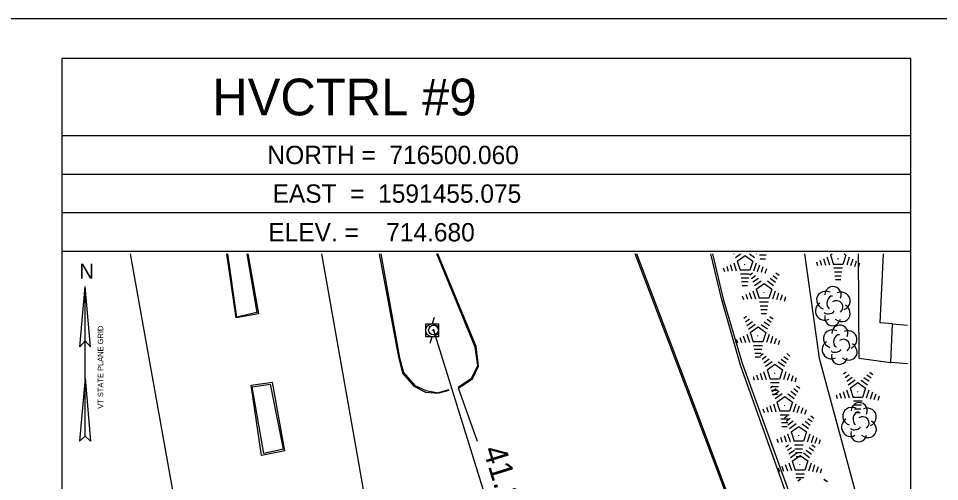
# Model space of a CAD drawing. Extents: x 1586965 to 1590952, y 716317 to 720029.
# Drawn here: x 1590701.5 to 1590820.9, y 716551.1 to 716611 of the extents above; entities that cross this region are included whole.
import ezdxf

# ---------------------------------------------------------------- set-up
doc = ezdxf.new("R2010")
doc.units = 0
for name, color, linetype in [('CBP', 7, 'Continuous'), ('Default', 7, 'Continuous'), ('LBF', 7, 'Continuous'), ('LS', 7, 'Continuous'), ('LSH', 7, 'Continuous'), ('LTC', 7, 'Continuous'), ('LW', 7, 'Continuous'), ('LWS', 7, 'Continuous'), ('NBL2', 7, 'Continuous'), ('NNA_P', 7, 'Continuous'), ('PET', 7, 'Continuous'), ('RC', 7, 'Continuous'), ('RDP', 7, 'Continuous'), ('RSW', 7, 'Continuous'), ('UP', 7, 'Continuous')]:
    doc.layers.add(name, color=color, linetype=linetype)

msp = doc.modelspace()

# ---------------------------------------------------------------- linework, layer by layer
at = {"layer": 'CBP'}
for radius in [0.625, 0.0833]:
    msp.add_circle((1590755.32, 716570.71), radius, dxfattribs=at)
at = {"layer": 'Default'}
msp.add_line((1590755.32, 716570.71), (1590767.54, 716531.39), dxfattribs=at)
at = {"layer": 'LBF'}
msp.add_lwpolyline([(1590816.72, 716566.34), (1590814.58, 716566.5), (1590814.8, 716571.53), (1590816.72, 716571.34)], dxfattribs=at)
at = {"layer": 'LS'}
for points in [[(1590731.12, 716580.57), (1590732.43, 716572.99), (1590729.83, 716572.39), (1590728.68, 716580.57)], [(1590735.9, 716555.28), (1590733.33, 716554.73), (1590731.81, 716563.38), (1590734.22, 716563.7)], [(1590735.9, 716555.28), (1590734.22, 716563.7)]]:
    msp.add_lwpolyline(points, dxfattribs=at)
at = {"layer": 'LSH'}
for p, q in [((1590807.04, 716573.86), (1590807.04, 716573.86)), ((1590807.04, 716573.86), (1590807.04, 716573.86)), ((1590807.93, 716568.86), (1590807.93, 716568.86)), ((1590807.93, 716568.86), (1590807.93, 716568.86)), ((1590810.43, 716558.84), (1590810.43, 716558.84)), ((1590810.43, 716558.84), (1590810.43, 716558.84))]:
    msp.add_line(p, q, dxfattribs=at)
for centre in [(1590807.09, 716575.29), (1590807.97, 716570.3), (1590810.48, 716560.28)]:
    msp.add_arc(centre, 1.05, 335.5272, 180.9563, dxfattribs=at)
for centre, major_axis, ratio, start_param, end_param in [((1590806.25, 716574.52), (1.21, -0.51), 0.895232, 1.570796, 4.712389), ((1590806.83, 716574.31), (-0.208, -0.792), 0.645439, 3.141593, 6.283185), ((1590808.08, 716574.44), (-1.14, -0.48), 0.949671, 1.570796, 4.712389), ((1590805.96, 716573.15), (0.58, -1.04), 0.959034, 3.141593, 6.283185), ((1590807.54, 716573.69), (-0.5, 0.667), 0.989748, 3.141593, 6.283185), ((1590808.04, 716573.02), (-1.09, 0.79), 0.841452, 1.570796, 4.712389), ((1590806.58, 716573.1), (-0.625, -0.083), 0.423636, 0, 3.141593), ((1590807.04, 716572.36), (0.26, 1.06), 0.942809, 1.570796, 4.712389), ((1590807.13, 716569.53), (1.21, -0.51), 0.895232, 1.570796, 4.712389), ((1590808.97, 716569.44), (-1.14, -0.48), 0.949671, 1.570796, 4.712389), ((1590806.84, 716568.15), (0.58, -1.04), 0.959034, 3.141593, 6.283185), ((1590807.72, 716569.32), (-0.208, -0.792), 0.645439, 3.141593, 6.283185), ((1590808.43, 716568.69), (-0.5, 0.667), 0.989748, 3.141593, 6.283185), ((1590807.47, 716568.11), (-0.625, -0.083), 0.423636, 0, 3.141593), ((1590808.93, 716568.03), (-1.09, 0.79), 0.841452, 1.570796, 4.712389), ((1590807.93, 716567.36), (0.26, 1.06), 0.942809, 1.570796, 4.712389), ((1590809.64, 716559.51), (1.21, -0.51), 0.895232, 1.570796, 4.712389), ((1590811.48, 716559.43), (-1.14, -0.48), 0.949671, 1.570796, 4.712389), ((1590810.23, 716559.3), (-0.208, -0.792), 0.645439, 3.141593, 6.283185), ((1590810.93, 716558.68), (-0.5, 0.667), 0.989748, 3.141593, 6.283185), ((1590809.35, 716558.13), (0.58, -1.04), 0.959034, 3.141593, 6.283185), ((1590811.43, 716558.01), (-1.09, 0.79), 0.841452, 1.570796, 4.712389), ((1590810.43, 716557.34), (0.26, 1.06), 0.942809, 1.570796, 4.712389), ((1590809.98, 716558.09), (-0.625, -0.083), 0.423636, 0, 3.141593)]:
    msp.add_ellipse(centre, major_axis=major_axis, ratio=ratio, start_param=start_param, end_param=end_param, dxfattribs=at)
at = {"layer": 'LTC'}
for p, q in [((1590794.24, 716580.55), (1590794.26, 716580.57)), ((1590794.45, 716580.09), (1590795.12, 716580.57)), ((1590794.67, 716579.63), (1590795.69, 716580.37)), ((1590795.69, 716580.37), (1590796.68, 716579.64)), ((1590796.26, 716580.57), (1590796.92, 716580.09)), ((1590797.11, 716580.57), (1590797.16, 716580.53)), ((1590798.41, 716580.39), (1590797.58, 716580.39)), ((1590798.33, 716579.89), (1590797.65, 716579.89)), ((1590805.84, 716579.96), (1590806.11, 716579.12)), ((1590806.3, 716580.18), (1590806.63, 716579.16)), ((1590806.75, 716580.4), (1590806.99, 716580.57)), ((1590806.75, 716580.4), (1590807.14, 716579.2)), ((1590808.76, 716580.41), (1590808.37, 716579.2)), ((1590808.53, 716580.57), (1590808.76, 716580.41)), ((1590809.2, 716580.13), (1590808.86, 716579.09)), ((1590809.64, 716579.88), (1590809.35, 716579)), ((1590792.85, 716578.76), (1590793.01, 716578.3)), ((1590793.31, 716578.98), (1590793.52, 716578.33)), ((1590793.76, 716579.2), (1590794.04, 716578.36)), ((1590794.22, 716579.41), (1590794.55, 716578.39)), ((1590794.67, 716579.63), (1590795.06, 716578.44)), ((1590796.68, 716579.64), (1590796.29, 716578.44)), ((1590797.12, 716579.37), (1590796.78, 716578.33)), ((1590797.57, 716579.12), (1590797.28, 716578.24)), ((1590798.01, 716578.87), (1590797.77, 716578.14)), ((1590798.45, 716578.62), (1590798.27, 716578.05)), ((1590804.93, 716579.53), (1590805.08, 716579.06)), ((1590805.39, 716579.74), (1590805.6, 716579.09)), ((1590808.37, 716579.2), (1590807.14, 716579.2)), ((1590808.33, 716578.7), (1590807.19, 716578.7)), ((1590810.09, 716579.63), (1590809.85, 716578.9)), ((1590810.53, 716579.38), (1590810.34, 716578.81)), ((1590796.29, 716578.44), (1590795.06, 716578.44)), ((1590796.25, 716577.94), (1590795.11, 716577.94)), ((1590796.17, 716577.44), (1590795.18, 716577.44)), ((1590796.3, 716577.86), (1590796.65, 716578.12)), ((1590796.51, 716577.4), (1590797.03, 716577.78)), ((1590796.72, 716576.93), (1590797.42, 716577.44)), ((1590799.32, 716577.75), (1590799.87, 716577.36)), ((1590799.69, 716578.1), (1590800.11, 716577.8)), ((1590808.25, 716578.2), (1590807.26, 716578.2)), ((1590808.16, 716577.7), (1590807.33, 716577.7)), ((1590796.09, 716576.94), (1590795.25, 716576.94)), ((1590796, 716576.44), (1590795.33, 716576.44)), ((1590796.92, 716576.47), (1590797.8, 716577.1)), ((1590797.15, 716576.01), (1590798.16, 716576.75)), ((1590798.16, 716576.75), (1590799.16, 716576.02)), ((1590798.58, 716577.06), (1590799.39, 716576.47)), ((1590798.95, 716577.41), (1590799.63, 716576.91)), ((1590808.08, 716577.2), (1590807.4, 716577.2)), ((1590795.33, 716575.14), (1590795.48, 716574.67)), ((1590795.78, 716575.36), (1590796, 716574.71)), ((1590796.24, 716575.58), (1590796.51, 716574.74)), ((1590796.69, 716575.79), (1590797.03, 716574.77)), ((1590797.15, 716576.01), (1590797.54, 716574.82)), ((1590799.16, 716576.02), (1590798.77, 716574.82)), ((1590799.6, 716575.75), (1590799.26, 716574.71)), ((1590800.04, 716575.5), (1590799.75, 716574.61)), ((1590800.48, 716575.25), (1590800.25, 716574.52)), ((1590798.77, 716574.82), (1590797.54, 716574.82)), ((1590798.73, 716574.32), (1590797.58, 716574.32)), ((1590800.93, 716575), (1590800.74, 716574.42)), ((1590798.64, 716573.82), (1590797.66, 716573.82)), ((1590798.56, 716573.32), (1590797.73, 716573.32)), ((1590798.48, 716572.82), (1590797.8, 716572.82)), ((1590795.52, 716572.24), (1590795.87, 716572.5)), ((1590795.73, 716571.77), (1590796.26, 716572.16)), ((1590795.94, 716571.31), (1590796.64, 716571.82)), ((1590796.15, 716570.84), (1590797.02, 716571.48)), ((1590798.17, 716571.78), (1590798.85, 716571.29)), ((1590798.54, 716572.13), (1590799.09, 716571.73)), ((1590798.92, 716572.48), (1590799.33, 716572.18)), ((1590796.37, 716570.39), (1590797.38, 716571.12)), ((1590796.37, 716570.39), (1590796.76, 716569.19)), ((1590797.38, 716571.12), (1590798.38, 716570.4)), ((1590797.8, 716571.44), (1590798.61, 716570.85)), ((1590798.38, 716570.4), (1590797.99, 716569.19)), ((1590794.55, 716569.52), (1590794.7, 716569.05)), ((1590795, 716569.74), (1590795.22, 716569.08)), ((1590795.46, 716569.95), (1590795.73, 716569.12)), ((1590795.92, 716570.17), (1590796.25, 716569.15)), ((1590797.99, 716569.19), (1590796.76, 716569.19)), ((1590798.82, 716570.13), (1590798.48, 716569.09)), ((1590799.26, 716569.88), (1590798.97, 716568.99)), ((1590799.71, 716569.63), (1590799.47, 716568.9)), ((1590800.15, 716569.38), (1590799.96, 716568.8)), ((1590797.95, 716568.69), (1590796.8, 716568.69)), ((1590797.87, 716568.19), (1590796.88, 716568.19)), ((1590797.78, 716567.69), (1590796.95, 716567.69)), ((1590797.7, 716567.19), (1590797.02, 716567.19)), ((1590797.7, 716567.42), (1590798.05, 716567.67)), ((1590797.9, 716566.95), (1590798.43, 716567.33)), ((1590798.11, 716566.48), (1590798.82, 716567)), ((1590800.35, 716566.96), (1590801.03, 716566.47)), ((1590800.72, 716567.31), (1590801.27, 716566.91)), ((1590801.09, 716567.66), (1590801.51, 716567.35)), ((1590798.32, 716566.02), (1590799.2, 716566.66)), ((1590798.55, 716565.56), (1590799.56, 716566.3)), ((1590798.55, 716565.56), (1590798.94, 716564.37)), ((1590799.56, 716566.3), (1590800.56, 716565.57)), ((1590799.98, 716566.61), (1590800.79, 716566.02)), ((1590800.56, 716565.57), (1590800.17, 716564.37)), ((1590796.73, 716564.7), (1590796.88, 716564.23)), ((1590797.18, 716564.91), (1590797.39, 716564.26)), ((1590797.64, 716565.13), (1590797.91, 716564.29)), ((1590798.09, 716565.34), (1590798.42, 716564.33)), ((1590800.17, 716564.37), (1590798.94, 716564.37)), ((1590800.99, 716565.3), (1590800.66, 716564.26)), ((1590801.44, 716565.05), (1590801.15, 716564.17)), ((1590801.88, 716564.8), (1590801.65, 716564.07)), ((1590802.33, 716564.55), (1590802.14, 716563.98)), ((1590808.44, 716565.03), (1590808.8, 716565.29)), ((1590808.65, 716564.57), (1590809.18, 716564.95)), ((1590808.86, 716564.1), (1590809.57, 716564.61)), ((1590811.1, 716564.58), (1590811.78, 716564.08)), ((1590811.47, 716564.92), (1590812.02, 716564.53)), ((1590811.84, 716565.27), (1590812.26, 716564.97)), ((1590798.97, 716563.24), (1590799.32, 716563.5)), ((1590800.13, 716563.87), (1590798.98, 716563.87)), ((1590800.04, 716563.37), (1590799.06, 716563.37)), ((1590799.18, 716562.78), (1590799.71, 716563.16)), ((1590802, 716563.13), (1590802.54, 716562.73)), ((1590802.37, 716563.48), (1590802.79, 716563.18)), ((1590809.07, 716563.64), (1590809.95, 716564.27)), ((1590809.3, 716563.18), (1590810.31, 716563.91)), ((1590809.3, 716563.18), (1590809.68, 716561.99)), ((1590810.31, 716563.91), (1590811.3, 716563.19)), ((1590810.73, 716564.23), (1590811.54, 716563.64)), ((1590811.3, 716563.19), (1590810.91, 716561.99)), ((1590799.96, 716562.87), (1590799.13, 716562.87)), ((1590799.88, 716562.37), (1590799.2, 716562.37)), ((1590799.39, 716562.31), (1590800.09, 716562.82)), ((1590799.6, 716561.84), (1590800.48, 716562.48)), ((1590799.82, 716561.39), (1590800.83, 716562.12)), ((1590800.83, 716562.12), (1590801.83, 716561.4)), ((1590801.25, 716562.44), (1590802.06, 716561.85)), ((1590801.62, 716562.79), (1590802.3, 716562.29)), ((1590807.48, 716562.31), (1590807.63, 716561.84)), ((1590807.93, 716562.53), (1590808.14, 716561.88)), ((1590808.39, 716562.74), (1590808.66, 716561.91)), ((1590808.84, 716562.96), (1590809.17, 716561.94)), ((1590810.91, 716561.99), (1590809.68, 716561.99)), ((1590811.74, 716562.92), (1590811.4, 716561.88)), ((1590812.19, 716562.67), (1590811.9, 716561.78)), ((1590812.63, 716562.42), (1590812.39, 716561.69)), ((1590813.08, 716562.17), (1590812.89, 716561.59)), ((1590798.46, 716560.74), (1590798.67, 716560.09)), ((1590798.91, 716560.95), (1590799.18, 716560.12)), ((1590799.37, 716561.17), (1590799.7, 716560.15)), ((1590799.82, 716561.39), (1590800.21, 716560.2)), ((1590801.83, 716561.4), (1590801.44, 716560.2)), ((1590802.27, 716561.13), (1590801.93, 716560.09)), ((1590802.71, 716560.88), (1590802.42, 716559.99)), ((1590810.88, 716561.49), (1590809.73, 716561.49)), ((1590810.79, 716560.99), (1590809.8, 716560.99)), ((1590798, 716560.52), (1590798.15, 716560.05)), ((1590801.44, 716560.2), (1590800.21, 716560.2)), ((1590801.4, 716559.7), (1590800.26, 716559.7)), ((1590800.8, 716559.37), (1590801.16, 716559.63)), ((1590803.16, 716560.63), (1590802.92, 716559.9)), ((1590803.6, 716560.38), (1590803.41, 716559.8)), ((1590804.2, 716559.61), (1590804.62, 716559.31)), ((1590810.71, 716560.49), (1590809.88, 716560.49)), ((1590810.62, 716559.99), (1590809.95, 716559.99)), ((1590801.32, 716559.2), (1590800.33, 716559.2)), ((1590801.23, 716558.7), (1590800.4, 716558.7)), ((1590801.01, 716558.9), (1590801.54, 716559.29)), ((1590801.22, 716558.44), (1590801.92, 716558.95)), ((1590801.43, 716557.97), (1590802.31, 716558.61)), ((1590803.09, 716558.57), (1590803.9, 716557.98)), ((1590803.46, 716558.91), (1590804.14, 716558.42)), ((1590803.83, 716559.26), (1590804.38, 716558.86)), ((1590801.15, 716558.2), (1590800.47, 716558.2)), ((1590801.2, 716557.3), (1590801.53, 716556.28)), ((1590801.65, 716557.52), (1590802.67, 716558.25)), ((1590801.65, 716557.52), (1590802.04, 716556.32)), ((1590802.67, 716558.25), (1590803.66, 716557.53)), ((1590803.66, 716557.53), (1590803.27, 716556.32)), ((1590804.1, 716557.26), (1590803.76, 716556.22)), ((1590799.83, 716556.65), (1590799.99, 716556.18)), ((1590800.29, 716556.87), (1590800.5, 716556.21)), ((1590800.74, 716557.08), (1590801.02, 716556.25)), ((1590803.27, 716556.32), (1590802.04, 716556.32)), ((1590804.54, 716557.01), (1590804.26, 716556.12)), ((1590804.99, 716556.76), (1590804.75, 716556.03)), ((1590805.43, 716556.51), (1590805.25, 716555.93)), ((1590800.96, 716555.61), (1590801.32, 716555.87)), ((1590801.17, 716555.15), (1590801.7, 716555.53)), ((1590801.38, 716554.68), (1590802.08, 716555.19)), ((1590801.59, 716554.22), (1590802.47, 716554.86)), ((1590803.23, 716555.82), (1590802.09, 716555.82)), ((1590803.15, 716555.32), (1590802.16, 716555.32)), ((1590803.07, 716554.82), (1590802.23, 716554.82)), ((1590803.25, 716554.81), (1590804.06, 716554.22)), ((1590803.62, 716555.16), (1590804.3, 716554.66)), ((1590803.99, 716555.51), (1590804.54, 716555.11)), ((1590804.36, 716555.86), (1590804.78, 716555.55)), ((1590801.36, 716553.54), (1590801.69, 716552.52)), ((1590801.81, 716553.76), (1590802.83, 716554.5)), ((1590801.81, 716553.76), (1590802.2, 716552.57)), ((1590802.98, 716554.32), (1590802.31, 716554.32)), ((1590802.83, 716554.5), (1590803.82, 716553.77)), ((1590803.82, 716553.77), (1590803.43, 716552.57)), ((1590799.99, 716552.89), (1590800.15, 716552.43)), ((1590800.45, 716553.11), (1590800.66, 716552.46)), ((1590800.9, 716553.33), (1590801.18, 716552.49)), ((1590803.43, 716552.57), (1590802.2, 716552.57)), ((1590804.26, 716553.5), (1590803.92, 716552.46)), ((1590804.7, 716553.25), (1590804.42, 716552.37)), ((1590805.15, 716553), (1590804.91, 716552.27)), ((1590805.59, 716552.75), (1590805.41, 716552.18)), ((1590803.39, 716552.07), (1590802.25, 716552.07)), ((1590803.31, 716551.57), (1590802.32, 716551.57)), ((1590802.51, 716551.19), (1590802.87, 716551.44)), ((1590802.54, 716551.18), (1590802.89, 716551.43)), ((1590805.91, 716551.43), (1590806.33, 716551.12)), ((1590805.94, 716551.42), (1590806.36, 716551.11))]:
    msp.add_line(p, q, dxfattribs=at)
at = {"layer": 'LW'}
msp.add_lwpolyline([(1590816.72, 716513.27), (1590815.7, 716513.71), (1590814.67, 716514.44), (1590811.44, 716522.23), (1590806.32, 716536.3), (1590802.62, 716546.4), (1590795.37, 716566.37), (1590792.94, 716574.53), (1590791.51, 716580.57)], dxfattribs=at)
at = {"layer": 'LWS'}
msp.add_lwpolyline([(1590803.38, 716580.57), (1590805.28, 716567.09), (1590811.16, 716545.37), (1590814.07, 716536.23), (1590815.3, 716534.63), (1590816.72, 716534.63)], dxfattribs=at)
at = {"layer": 'NBL2'}
for p, q in [((1590312.19, 716611.03), (1590952.19, 716611.03)), ((1590817.19, 716595.86), (1590707.19, 716595.86)), ((1590817.19, 716590.86), (1590707.19, 716590.86)), ((1590817.19, 716585.86), (1590707.19, 716585.86)), ((1590817.19, 716580.86), (1590707.19, 716580.86))]:
    msp.add_line(p, q, dxfattribs=at)
msp.add_lwpolyline([(1590707.19, 716489.86), (1590817.19, 716489.86), (1590817.19, 716605.86), (1590707.19, 716605.86)], close=True, dxfattribs=at)
at = {"layer": 'NNA_P'}
for p, q in [((1590709.48, 716568.55), (1590710.18, 716576.34)), ((1590710.18, 716556.97), (1590710.18, 716576.34)), ((1590710.87, 716568.55), (1590710.18, 716576.34)), ((1590709.48, 716568.55), (1590710.18, 716569.31)), ((1590710.87, 716568.55), (1590710.18, 716569.31)), ((1590710.18, 716564.49), (1590709.46, 716556.33)), ((1590710.18, 716564.49), (1590710.9, 716556.33)), ((1590710.18, 716556.97), (1590709.46, 716556.33)), ((1590710.18, 716556.97), (1590710.9, 716556.33))]:
    msp.add_line(p, q, dxfattribs=at)
at = {"layer": 'PET'}
for points in [[(1590761.02, 716556.28), (1590758.58, 716563.19), (1590760.37, 716564.4), (1590761.15, 716566.03), (1590760.84, 716568.57), (1590755.88, 716580.57)], [(1590816.72, 716501.87), (1590815.38, 716502.54), (1590813.44, 716503.83), (1590810.82, 716506.6), (1590809.07, 716509.13), (1590807.86, 716511.61), (1590807.26, 716513.17), (1590805.73, 716517.09), (1590799.48, 716533.06), (1590789.21, 716560.16), (1590781.44, 716580.57)]]:
    msp.add_lwpolyline(points, dxfattribs=at)
at = {"layer": 'RC'}
for points in [[(1590748.48, 716580.57), (1590750.92, 716567.1), (1590751.45, 716565.22), (1590752.91, 716563.54), (1590754.31, 716562.87), (1590755.96, 716562.6)], [(1590758.58, 716563.35), (1590760.23, 716564.47), (1590761.07, 716566.13), (1590760.73, 716568.48), (1590755.74, 716580.57)], [(1590816.72, 716502.02), (1590815.53, 716502.54), (1590813.56, 716504.04), (1590811.02, 716506.63), (1590809.18, 716509.24), (1590808, 716511.55), (1590807.33, 716513.31), (1590805.92, 716517.2), (1590799.59, 716533.11), (1590789.46, 716560.15), (1590781.65, 716580.57)], [(1590758.58, 716563.35), (1590758.54, 716563.34)], [(1590757.27, 716562.98), (1590755.96, 716562.6)]]:
    msp.add_lwpolyline(points, dxfattribs=at)
at = {"layer": 'RDP'}
for points in [[(1590716.01, 716580.57), (1590722.65, 716543.71), (1590718.57, 716542.63), (1590720.31, 716531.18), (1590748.7, 716535.86)], [(1590731.25, 716580.57), (1590732.65, 716572.83), (1590729.77, 716572.28), (1590728.56, 716580.57)], [(1590740.82, 716580.57), (1590745.38, 716554.72), (1590748.7, 716535.86)], [(1590748.3, 716580.57), (1590750.77, 716567.22), (1590751.32, 716565.14), (1590752.79, 716563.47), (1590754.27, 716562.69), (1590756.02, 716562.55)], [(1590736.08, 716555.07), (1590733.06, 716554.48), (1590731.69, 716563.58), (1590734.46, 716563.96)], [(1590736.08, 716555.07), (1590734.46, 716563.96)], [(1590757.3, 716562.87), (1590756.02, 716562.55)]]:
    msp.add_lwpolyline(points, dxfattribs=at)
at = {"layer": 'RSW'}
for points in [[(1590805.54, 716519.53), (1590811.23, 716522.1), (1590806, 716536.21), (1590802.2, 716546.34), (1590795.11, 716566.17), (1590792.7, 716574.61), (1590791.27, 716580.57)], [(1590810.36, 716580.57), (1590810.45, 716567.09), (1590814.58, 716566.5)], [(1590814.8, 716571.53), (1590813.21, 716571.65), (1590813.62, 716580.57)]]:
    msp.add_lwpolyline(points, dxfattribs=at)
at = {"layer": 'UP'}
for p, q in [((1590754.32, 716569.84), (1590754.32, 716571.51)), ((1590754.32, 716571.51), (1590755.98, 716571.51)), ((1590755.4, 716572.34), (1590755.15, 716571.51)), ((1590755.98, 716571.51), (1590755.98, 716569.84)), ((1590755.15, 716570.68), (1590755.15, 716570.68)), ((1590755.98, 716569.84), (1590754.32, 716569.84)), ((1590754.9, 716569.01), (1590755.15, 716569.84))]:
    msp.add_line(p, q, dxfattribs=at)
msp.add_circle((1590755.15, 716570.68), 0.833, dxfattribs=at)

# ---------------------------------------------------------------- texts
at = {"layer": 'Default'}
msp.add_text('41.18', height=3, rotation=287.2596, dxfattribs=at).set_placement((1590761.7, 716555.24))
at = {"layer": 'LTC'}
for p in [(1590807.65, 716580.14), (1590795.57, 716579.38), (1590798.04, 716575.76), (1590797.26, 716570.14), (1590799.44, 716565.31), (1590810.19, 716562.93), (1590800.72, 716561.14), (1590802.55, 716557.27), (1590802.71, 716553.51)]:
    msp.add_text('.', height=1.04, rotation=270, dxfattribs=at).set_placement(p)
at = {"layer": 'NBL2'}
for s, height, p in [('     HVCTRL #9     ', 4.75, (1590717.84, 716598.49)), ('NORTH =  716500.060 ', 2.375, (1590733.81, 716592.18)), ('EAST  =  1591455.075', 2.375, (1590734.47, 716587.18)), ('ELEV. =    714.680  ', 2.375, (1590733.92, 716582.18))]:
    msp.add_text(s, height=height, dxfattribs=at).set_placement(p)
at = {"layer": 'NNA_P'}
msp.add_text('N', height=1.97, dxfattribs=at).set_placement((1590709.42, 716577.35))
msp.add_text('VT STATE PLANE GRID', height=0.7, rotation=90.0204, dxfattribs=at).set_placement((1590712.53, 716560.53))

doc.saveas('drawing.dxf')
